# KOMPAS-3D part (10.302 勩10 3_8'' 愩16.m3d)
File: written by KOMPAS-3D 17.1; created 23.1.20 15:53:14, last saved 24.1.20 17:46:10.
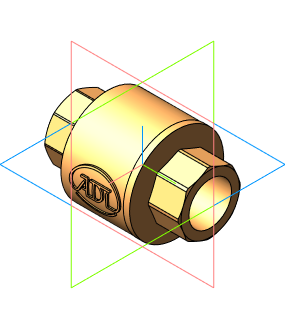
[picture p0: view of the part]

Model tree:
1. Операция без истории:2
